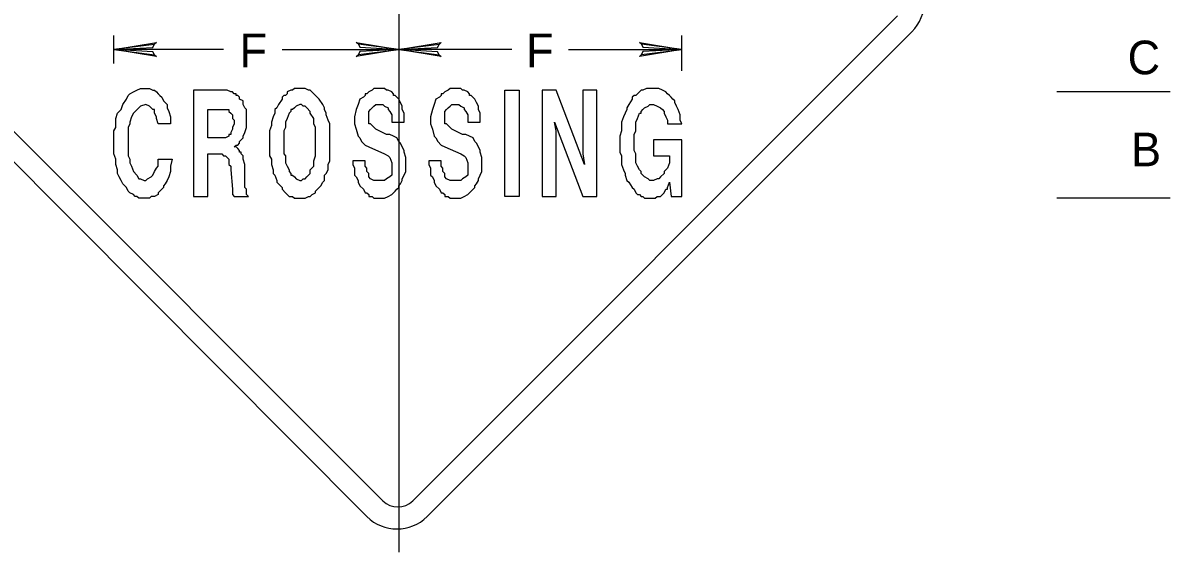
# Model space of a CAD drawing. Extents: x 0.013 to 0.191, y 0.004 to 0.259.
# Drawn here: x 0.0806 to 0.1616, y 0.1184 to 0.1557 of the extents above; entities that cross this region are included whole.
import ezdxf

# ---------------------------------------------------------------- set-up
doc = ezdxf.new("R2010")
doc.units = 0
doc.layers.add('1', color=7, linetype='Continuous')
doc.layers.add('3', color=7, linetype='Continuous')

# ---------------------------------------------------------------- blocks, each defined once
blk = doc.blocks.new('RARROW')
at = {"layer": '3'}
for p, q in [((-2.156, 0.28500000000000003), (-2.2665, 0.384625)), ((-2.2665, 0.384625), (0, 0)), ((0, 0), (-2.2665, -0.379125)), ((-2.156, 0.28500000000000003), (-2.075625, 0.12075)), ((0, 0), (-2.156, 0.28500000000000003)), ((-2.14975, -0.2705), (0, 0)), ((-2.075625, 0.12075), (0, 0)), ((0, 0), (-2.074, -0.108)), ((-2.2665, -0.379125), (-2.14975, -0.2705)), ((-2.074, -0.108), (-2.14975, -0.2705))]:
    blk.add_line(p, q, dxfattribs=at)

msp = doc.modelspace()

# ---------------------------------------------------------------- linework, layer by layer
at = {"layer": '1'}
for p, q in [((0.161625, 0.150875), (0.153625, 0.150875)), ((0.161625, 0.143375), (0.153625, 0.143375))]:
    msp.add_line(p, q, dxfattribs=at)
msp.add_lwpolyline([(0.125, 0.151125), (0.124875, 0.151125)], dxfattribs=at)
at = {"layer": '3'}
for p, q in [((0.107125, 0.1975), (0.107125, 0.11837500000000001)), ((0.107125, 0.15687500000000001), (0.107125, 0.154875)), ((0.106, 0.122), (0.07175000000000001, 0.15625)), ((0.142375, 0.15625), (0.108125, 0.122)), ((0.104875, 0.120875), (0.07062500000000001, 0.15525)), ((0.08700000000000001, 0.152875), (0.08700000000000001, 0.154875)), ((0.143375, 0.155125), (0.109125, 0.120875)), ((0.12712500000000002, 0.152375), (0.12712500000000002, 0.154875)), ((0.09475, 0.153875), (0.08700000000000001, 0.153875)), ((0.098875, 0.153875), (0.107125, 0.153875)), ((0.115125, 0.153875), (0.107125, 0.153875)), ((0.11912500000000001, 0.153875), (0.12712500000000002, 0.153875))]:
    msp.add_line(p, q, dxfattribs=at)
for points in [[(0.08700000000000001, 0.147375), (0.08700000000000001, 0.14775), (0.08700000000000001, 0.148125), (0.08712500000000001, 0.148375), (0.08712500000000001, 0.148625), (0.08712500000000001, 0.149), (0.08725000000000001, 0.149375), (0.08750000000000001, 0.149625), (0.08762500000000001, 0.15), (0.08787500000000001, 0.150375), (0.088, 0.150625), (0.088125, 0.15075), (0.088375, 0.150875), (0.088625, 0.151), (0.088875, 0.151125), (0.089125, 0.151125), (0.08925, 0.151125), (0.0895, 0.151125), (0.08975, 0.151), (0.089875, 0.151), (0.09, 0.150875), (0.090125, 0.15075), (0.09025, 0.150625), (0.090375, 0.1505), (0.0905, 0.15025), (0.09075, 0.15), (0.09075, 0.14975), (0.090875, 0.1495), (0.091, 0.149125), (0.091, 0.148625)], [(0.095, 0.151), (0.092625, 0.151), (0.092625, 0.14350000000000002), (0.093625, 0.14350000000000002), (0.093625, 0.1465), (0.0945, 0.1465)], [(0.0965, 0.14350000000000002), (0.096375, 0.143625), (0.096375, 0.14375000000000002), (0.096375, 0.14400000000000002), (0.09625, 0.144125), (0.09625, 0.14425), (0.09625, 0.145625), (0.09625, 0.14575), (0.096125, 0.146125), (0.096125, 0.14625), (0.096125, 0.146375), (0.096, 0.1465), (0.096, 0.146625), (0.095875, 0.146625), (0.095875, 0.14675), (0.09575, 0.146875), (0.09575, 0.146875), (0.095625, 0.147), (0.0955, 0.147), (0.095625, 0.147125), (0.09575, 0.147125), (0.095875, 0.14725), (0.095875, 0.147375), (0.096125, 0.147625), (0.096125, 0.14775), (0.09625, 0.148), (0.096375, 0.148375), (0.096375, 0.1485), (0.096375, 0.148625), (0.096375, 0.148875), (0.096375, 0.149125), (0.096375, 0.149375), (0.096375, 0.149625), (0.09625, 0.14975), (0.096125, 0.15), (0.096125, 0.15), (0.096125, 0.15025), (0.095875, 0.150375), (0.095875, 0.1505), (0.09575, 0.150625), (0.095625, 0.150625), (0.095625, 0.15075), (0.0955, 0.15075), (0.095375, 0.150875), (0.09525, 0.150875), (0.095, 0.151)], [(0.100125, 0.151125), (0.09975, 0.151125), (0.099625, 0.151), (0.0995, 0.151), (0.09925, 0.150875), (0.09925, 0.15075), (0.099125, 0.150625), (0.099, 0.150625), (0.098875, 0.1505), (0.098875, 0.150375), (0.098625, 0.15), (0.0985, 0.14975), (0.098375, 0.149625), (0.098375, 0.149375), (0.09825, 0.149125), (0.098125, 0.14875), (0.098125, 0.1485), (0.098, 0.148125), (0.098, 0.147625), (0.098, 0.147375), (0.098, 0.14725)], [(0.10225000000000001, 0.14725), (0.10225000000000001, 0.147625), (0.10225000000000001, 0.14775), (0.10225000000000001, 0.148125), (0.10225000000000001, 0.148375), (0.10225000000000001, 0.148625), (0.10212500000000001, 0.148875), (0.10200000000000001, 0.14925), (0.10200000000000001, 0.149375), (0.10187500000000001, 0.149625), (0.10187500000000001, 0.14975), (0.10175000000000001, 0.15), (0.1015, 0.150375), (0.10125, 0.150625), (0.101125, 0.15075), (0.100875, 0.151), (0.10075, 0.151), (0.1005, 0.151125), (0.10025, 0.151125), (0.100125, 0.151125)], [(0.106875, 0.150625), (0.10675, 0.150625), (0.10675, 0.15075), (0.106625, 0.150875), (0.106375, 0.151), (0.10625, 0.151), (0.106125, 0.151125), (0.105875, 0.151125), (0.10575, 0.151125), (0.105625, 0.151125), (0.105375, 0.151125), (0.10525, 0.151), (0.105, 0.150875), (0.104875, 0.15075), (0.10475, 0.15075), (0.10475, 0.150625), (0.104625, 0.1505)], [(0.11225, 0.150625), (0.112125, 0.150625), (0.112125, 0.15075), (0.112, 0.150875), (0.11175, 0.151), (0.111625, 0.151), (0.1115, 0.151125), (0.11125, 0.151125), (0.111125, 0.151125), (0.111, 0.151125), (0.11075, 0.151125), (0.110625, 0.151), (0.110375, 0.150875), (0.11025, 0.15075), (0.110125, 0.15075), (0.110125, 0.150625), (0.11, 0.1505)], [(0.114625, 0.14350000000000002), (0.114625, 0.151), (0.115625, 0.151), (0.115625, 0.14350000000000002), (0.114625, 0.14350000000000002)], [(0.11725000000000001, 0.151), (0.11725000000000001, 0.14350000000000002), (0.11825000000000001, 0.14350000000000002), (0.11825000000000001, 0.148125), (0.11812500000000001, 0.14875), (0.120125, 0.14350000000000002), (0.121125, 0.14350000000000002), (0.121125, 0.151), (0.120125, 0.151), (0.120125, 0.1465), (0.12025, 0.14575), (0.11825000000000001, 0.151), (0.11725000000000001, 0.151)], [(0.125, 0.151125), (0.124625, 0.151125), (0.124375, 0.151), (0.12425, 0.151), (0.124125, 0.150875), (0.124, 0.15075), (0.123875, 0.150625), (0.12375, 0.150625), (0.123625, 0.1505), (0.123625, 0.150375), (0.123375, 0.15), (0.12325, 0.14975), (0.12325, 0.149625), (0.123125, 0.149375), (0.123, 0.149125), (0.122875, 0.14875), (0.122875, 0.1485), (0.122875, 0.148125), (0.12275, 0.14775), (0.12275, 0.147375), (0.12275, 0.14725)], [(0.12712500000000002, 0.148625), (0.127, 0.148875), (0.127, 0.149125), (0.127, 0.14925), (0.12687500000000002, 0.149625), (0.12675, 0.149875), (0.12662500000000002, 0.150125), (0.12662500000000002, 0.15025), (0.1265, 0.150375), (0.12637500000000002, 0.1505), (0.12625, 0.150625), (0.12612500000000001, 0.15075), (0.126, 0.150875), (0.126, 0.150875), (0.12575, 0.151), (0.1255, 0.151125), (0.12525, 0.151125), (0.125, 0.151125)], [(0.090125, 0.148625), (0.09, 0.149), (0.09, 0.149125), (0.089875, 0.149375), (0.089875, 0.149625), (0.08975, 0.149625), (0.089625, 0.14975), (0.0895, 0.149875), (0.0895, 0.149875), (0.08925, 0.15), (0.08925, 0.15), (0.088875, 0.149875), (0.08875, 0.14975), (0.0885, 0.1495), (0.088375, 0.149375), (0.08825, 0.149125), (0.088125, 0.14875), (0.088125, 0.148625), (0.088, 0.148375), (0.088, 0.148125), (0.088, 0.14775), (0.088, 0.1475)], [(0.10025, 0.15), (0.100125, 0.15), (0.099875, 0.149875), (0.09975, 0.14975), (0.099625, 0.149625), (0.0995, 0.149625), (0.0995, 0.1495), (0.099375, 0.149375), (0.099375, 0.149375), (0.09925, 0.149), (0.099125, 0.14875), (0.099125, 0.1485), (0.099125, 0.148375), (0.099, 0.148125), (0.099, 0.147875), (0.099, 0.147625), (0.099, 0.1475), (0.099, 0.147375)], [(0.10125, 0.147375), (0.10125, 0.1475), (0.10125, 0.14775), (0.10125, 0.148), (0.10125, 0.148375), (0.101125, 0.148625), (0.101125, 0.149), (0.100875, 0.149375), (0.100875, 0.1495), (0.100625, 0.14975), (0.1005, 0.149875), (0.100375, 0.149875), (0.10025, 0.15), (0.10025, 0.15)], [(0.104625, 0.1505), (0.104375, 0.150375), (0.10425, 0.15), (0.104125, 0.149625), (0.10400000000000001, 0.149125), (0.10400000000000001, 0.148625), (0.104125, 0.14825), (0.10425, 0.14775), (0.104375, 0.147625), (0.1045, 0.147375), (0.10475, 0.147125), (0.105, 0.147), (0.106125, 0.1465), (0.106375, 0.146375), (0.1065, 0.14625), (0.106625, 0.145875), (0.106625, 0.145625), (0.106625, 0.1455)], [(0.105, 0.149), (0.105, 0.14925), (0.105, 0.1495), (0.105125, 0.149625), (0.10525, 0.14975), (0.105375, 0.149875), (0.1055, 0.15), (0.10575, 0.15), (0.106, 0.15), (0.106125, 0.149875), (0.106375, 0.14975), (0.106375, 0.149625), (0.1065, 0.1495), (0.106625, 0.14925), (0.106625, 0.14875)], [(0.106625, 0.14875), (0.1075, 0.14875), (0.1075, 0.149125), (0.1075, 0.149375), (0.107375, 0.149625), (0.107375, 0.149875), (0.10725, 0.150125), (0.107125, 0.150375), (0.106875, 0.150625)], [(0.11, 0.1505), (0.10975, 0.150375), (0.109625, 0.15), (0.1095, 0.149625), (0.109375, 0.149125), (0.109375, 0.148625), (0.1095, 0.14825), (0.109625, 0.14775), (0.10975, 0.147625), (0.109875, 0.147375), (0.110125, 0.147125), (0.110375, 0.147), (0.1115, 0.1465), (0.11175, 0.146375), (0.111875, 0.14625), (0.112, 0.145875), (0.112, 0.145625), (0.112, 0.1455)], [(0.110375, 0.149), (0.110375, 0.14925), (0.110375, 0.1495), (0.1105, 0.149625), (0.110625, 0.14975), (0.11075, 0.149875), (0.110875, 0.15), (0.111125, 0.15), (0.111375, 0.15), (0.1115, 0.149875), (0.11175, 0.14975), (0.11175, 0.149625), (0.111875, 0.1495), (0.112, 0.14925), (0.112, 0.14875)], [(0.112, 0.14875), (0.112875, 0.14875), (0.112875, 0.149125), (0.112875, 0.149375), (0.11275, 0.149625), (0.11275, 0.149875), (0.112625, 0.150125), (0.1125, 0.150375), (0.11225, 0.150625)], [(0.12375, 0.147375), (0.12375, 0.1475), (0.12375, 0.147625), (0.12375, 0.147875), (0.123875, 0.148125), (0.123875, 0.148375), (0.123875, 0.1485), (0.123875, 0.14875), (0.124, 0.149), (0.124125, 0.149375), (0.12425, 0.149375), (0.12425, 0.1495), (0.124375, 0.149625), (0.124375, 0.149625), (0.1245, 0.14975), (0.12475, 0.149875), (0.124875, 0.15), (0.125, 0.15)], [(0.125, 0.15), (0.12512500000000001, 0.15), (0.12537500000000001, 0.149875), (0.12562500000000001, 0.14975), (0.12575, 0.149625), (0.12587500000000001, 0.1495), (0.12587500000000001, 0.149375), (0.126, 0.149125), (0.12612500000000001, 0.148875), (0.12612500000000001, 0.148625)], [(0.094875, 0.147625), (0.093625, 0.147625), (0.093625, 0.149625), (0.094875, 0.149625)], [(0.094875, 0.149625), (0.095, 0.149625), (0.095125, 0.149625), (0.095125, 0.1495), (0.09525, 0.149375), (0.095375, 0.14925), (0.095375, 0.149125), (0.095375, 0.149), (0.0955, 0.148875), (0.0955, 0.148625), (0.0955, 0.148625), (0.095375, 0.148375), (0.095375, 0.14825), (0.09525, 0.148), (0.09525, 0.147875), (0.095125, 0.147875), (0.095125, 0.14775), (0.094875, 0.147625), (0.094875, 0.147625)], [(0.091, 0.148625), (0.090125, 0.148625)], [(0.1075, 0.145), (0.1075, 0.145), (0.107625, 0.14525), (0.107625, 0.1455), (0.107625, 0.145875), (0.107625, 0.146), (0.107625, 0.14625), (0.1075, 0.146625), (0.1075, 0.14675), (0.107375, 0.147), (0.10725, 0.14725), (0.107125, 0.147375), (0.107, 0.147625), (0.10675, 0.14775), (0.1065, 0.147875), (0.10625, 0.147875), (0.1055, 0.14825), (0.10525, 0.1485), (0.105125, 0.148625), (0.105, 0.148625), (0.105, 0.148875), (0.105, 0.149)], [(0.112875, 0.145), (0.112875, 0.145), (0.113, 0.14525), (0.113, 0.1455), (0.113, 0.145875), (0.113, 0.146), (0.113, 0.14625), (0.112875, 0.146625), (0.112875, 0.14675), (0.11275, 0.147), (0.112625, 0.14725), (0.1125, 0.147375), (0.112375, 0.147625), (0.112125, 0.14775), (0.111875, 0.147875), (0.111625, 0.147875), (0.110875, 0.14825), (0.110625, 0.1485), (0.1105, 0.148625), (0.110375, 0.148625), (0.110375, 0.148875), (0.110375, 0.149)], [(0.12612500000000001, 0.148625), (0.12712500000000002, 0.148625)], [(0.091125, 0.146125), (0.091, 0.145625), (0.091, 0.14525), (0.090875, 0.144875), (0.09075, 0.144625), (0.090625, 0.144375), (0.0905, 0.14425), (0.0905, 0.144125), (0.090375, 0.14400000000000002), (0.09025, 0.143875), (0.090125, 0.14375000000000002), (0.090125, 0.143625), (0.089875, 0.14350000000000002), (0.089875, 0.14350000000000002), (0.089625, 0.14350000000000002), (0.0895, 0.143375), (0.08925, 0.143375), (0.089, 0.143375), (0.08875, 0.143375), (0.088625, 0.14350000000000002), (0.0885, 0.14350000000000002), (0.088375, 0.143625), (0.088125, 0.14375000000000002), (0.088125, 0.14375000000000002), (0.088, 0.143875), (0.08787500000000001, 0.144125), (0.08762500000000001, 0.144375), (0.08750000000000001, 0.144625), (0.08737500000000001, 0.144875), (0.08725000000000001, 0.145125), (0.08725000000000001, 0.145375), (0.08712500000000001, 0.14575), (0.08712500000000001, 0.146125), (0.08700000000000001, 0.1465), (0.08700000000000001, 0.146875), (0.08700000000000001, 0.147375)], [(0.088, 0.1475), (0.088, 0.1475), (0.088, 0.147125), (0.088, 0.147), (0.088, 0.146625), (0.088, 0.146375), (0.088125, 0.146125), (0.088125, 0.145875), (0.08825, 0.145625), (0.088375, 0.14525), (0.088625, 0.145), (0.08875, 0.14475), (0.088875, 0.14475), (0.089125, 0.144625), (0.08925, 0.144625), (0.089375, 0.14475), (0.089625, 0.144875), (0.08975, 0.145), (0.089875, 0.14525), (0.09, 0.1455), (0.090125, 0.145625), (0.090125, 0.146125)], [(0.098, 0.14725), (0.098, 0.147), (0.098, 0.14675), (0.098, 0.146375), (0.098125, 0.146125), (0.098125, 0.145875), (0.098125, 0.14575), (0.09825, 0.145375), (0.09825, 0.145125), (0.098375, 0.145), (0.0985, 0.144625), (0.0985, 0.1445), (0.098875, 0.144125), (0.098875, 0.14400000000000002), (0.099125, 0.14375000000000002), (0.09925, 0.143625), (0.09925, 0.143625), (0.099375, 0.14350000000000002), (0.0995, 0.14350000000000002), (0.099625, 0.14350000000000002), (0.09975, 0.143375), (0.1, 0.143375), (0.10025, 0.143375), (0.10025, 0.143375), (0.1005, 0.143375), (0.10075, 0.14350000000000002), (0.100875, 0.14350000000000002), (0.101, 0.143625), (0.10125, 0.14375000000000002), (0.10125, 0.143875), (0.101375, 0.14400000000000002), (0.10162500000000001, 0.14425), (0.10175000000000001, 0.1445), (0.10187500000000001, 0.144625), (0.10187500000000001, 0.145), (0.10200000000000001, 0.145125), (0.10212500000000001, 0.145375), (0.10212500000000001, 0.14575), (0.10225000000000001, 0.146), (0.10225000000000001, 0.14625), (0.10225000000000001, 0.14675), (0.10225000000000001, 0.14725)], [(0.099, 0.147375), (0.099, 0.14725), (0.099, 0.147), (0.099, 0.14675), (0.099, 0.1465), (0.099125, 0.146375), (0.099125, 0.146125), (0.099125, 0.145875), (0.09925, 0.145625), (0.099375, 0.145375), (0.099375, 0.14525), (0.0995, 0.145125), (0.0995, 0.145), (0.099625, 0.145), (0.09975, 0.144875), (0.099875, 0.14475), (0.100125, 0.144625), (0.10025, 0.144625)], [(0.10025, 0.144625), (0.10025, 0.144625), (0.100375, 0.14475), (0.1005, 0.14475), (0.100625, 0.144875), (0.100875, 0.145125), (0.100875, 0.145375), (0.101125, 0.145625), (0.101125, 0.146), (0.10125, 0.146375), (0.10125, 0.146625), (0.10125, 0.146875), (0.10125, 0.14725), (0.10125, 0.147375)], [(0.12275, 0.14725), (0.12275, 0.147), (0.12275, 0.146625), (0.122875, 0.146375), (0.122875, 0.146125), (0.122875, 0.145875), (0.122875, 0.14575), (0.123, 0.145375), (0.123125, 0.145125), (0.123125, 0.145), (0.12325, 0.144625), (0.123375, 0.1445), (0.123625, 0.144125), (0.12375, 0.14400000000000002), (0.123875, 0.14375000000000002), (0.124, 0.143625), (0.124125, 0.143625), (0.12425, 0.14350000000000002), (0.12425, 0.14350000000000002), (0.124375, 0.14350000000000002), (0.1245, 0.143375), (0.12475, 0.143375), (0.125, 0.143375)], [(0.125, 0.144625), (0.124875, 0.144625), (0.12475, 0.14475), (0.1245, 0.144875), (0.124375, 0.145), (0.124375, 0.145), (0.12425, 0.145125), (0.12425, 0.14525), (0.124125, 0.145375), (0.124, 0.145625), (0.123875, 0.145875), (0.123875, 0.146125), (0.123875, 0.146375), (0.123875, 0.1465), (0.12375, 0.14675), (0.12375, 0.147), (0.12375, 0.14725), (0.12375, 0.147375)], [(0.12625, 0.1445), (0.12637500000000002, 0.14350000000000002), (0.12712500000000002, 0.14350000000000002), (0.12712500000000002, 0.1475), (0.12512500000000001, 0.1475), (0.12512500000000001, 0.146375), (0.12625, 0.146375)], [(0.090125, 0.146125), (0.091125, 0.146125)], [(0.0945, 0.1465), (0.094625, 0.1465), (0.09475, 0.146375), (0.094875, 0.146375), (0.095, 0.14625), (0.095125, 0.146125), (0.095125, 0.145875), (0.095125, 0.14575), (0.09525, 0.145625), (0.09525, 0.145375), (0.095375, 0.14400000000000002), (0.095375, 0.14400000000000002), (0.095375, 0.14375000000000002), (0.095375, 0.143625), (0.0955, 0.14350000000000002), (0.0955, 0.14350000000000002)], [(0.10475, 0.145875), (0.10475, 0.146), (0.10387500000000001, 0.146)], [(0.10387500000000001, 0.146), (0.10387500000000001, 0.14575), (0.10400000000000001, 0.1455), (0.10400000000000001, 0.14525), (0.10400000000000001, 0.145125), (0.10400000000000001, 0.145), (0.104125, 0.144875), (0.10425, 0.144625), (0.10425, 0.1445)], [(0.110125, 0.145875), (0.110125, 0.146), (0.10925, 0.146)], [(0.10925, 0.146), (0.10925, 0.14575), (0.109375, 0.1455), (0.109375, 0.14525), (0.109375, 0.145125), (0.109375, 0.145), (0.1095, 0.144875), (0.109625, 0.144625), (0.109625, 0.1445)], [(0.12625, 0.146375), (0.12625, 0.146125), (0.12625, 0.145875), (0.12612500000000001, 0.1455), (0.126, 0.145375), (0.12587500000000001, 0.14525), (0.12587500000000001, 0.145125), (0.12562500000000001, 0.144875), (0.1255, 0.14475), (0.12537500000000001, 0.14475), (0.12512500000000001, 0.144625), (0.125, 0.144625)], [(0.10625, 0.14475), (0.106125, 0.144625), (0.105875, 0.144625), (0.10575, 0.144625), (0.105625, 0.144625), (0.105375, 0.144625), (0.105125, 0.14475), (0.105, 0.144875), (0.105, 0.145125), (0.104875, 0.14525), (0.104875, 0.1455), (0.10475, 0.145625), (0.10475, 0.145875)], [(0.106625, 0.1455), (0.106625, 0.14525), (0.106625, 0.145), (0.1065, 0.144875), (0.10625, 0.14475)], [(0.111625, 0.14475), (0.1115, 0.144625), (0.11125, 0.144625), (0.111125, 0.144625), (0.111, 0.144625), (0.11075, 0.144625), (0.1105, 0.14475), (0.110375, 0.144875), (0.110375, 0.145125), (0.11025, 0.14525), (0.11025, 0.1455), (0.110125, 0.145625), (0.110125, 0.145875)], [(0.112, 0.1455), (0.112, 0.14525), (0.112, 0.145), (0.111875, 0.144875), (0.111625, 0.14475)], [(0.10425, 0.1445), (0.104375, 0.14425), (0.104625, 0.14400000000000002), (0.10475, 0.14375000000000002), (0.104875, 0.14375000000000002), (0.105, 0.143625), (0.105, 0.14350000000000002), (0.105125, 0.14350000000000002), (0.10525, 0.14350000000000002), (0.105375, 0.143375), (0.105625, 0.143375), (0.10575, 0.143375), (0.105875, 0.143375), (0.106125, 0.143375), (0.106375, 0.14350000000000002), (0.106375, 0.14350000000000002), (0.106625, 0.143625), (0.10675, 0.14375000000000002), (0.106875, 0.143875), (0.107, 0.14400000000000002), (0.107125, 0.144125), (0.107125, 0.14425), (0.10725, 0.144375), (0.107375, 0.144625), (0.107375, 0.14475), (0.1075, 0.145)], [(0.109625, 0.1445), (0.10975, 0.14425), (0.11, 0.14400000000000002), (0.110125, 0.14375000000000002), (0.11025, 0.14375000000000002), (0.110375, 0.143625), (0.110375, 0.14350000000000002), (0.1105, 0.14350000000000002), (0.110625, 0.14350000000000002), (0.11075, 0.143375), (0.111, 0.143375), (0.111125, 0.143375), (0.11125, 0.143375), (0.1115, 0.143375), (0.11175, 0.14350000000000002), (0.11175, 0.14350000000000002), (0.112, 0.143625), (0.112125, 0.14375000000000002), (0.11225, 0.143875), (0.112375, 0.14400000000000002), (0.1125, 0.144125), (0.1125, 0.14425), (0.112625, 0.144375), (0.11275, 0.144625), (0.11275, 0.14475), (0.112875, 0.145)], [(0.125, 0.143375), (0.125, 0.143375), (0.12525, 0.143375), (0.12537500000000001, 0.14350000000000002), (0.12562500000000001, 0.14350000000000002), (0.12562500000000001, 0.14350000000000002), (0.12575, 0.143625), (0.12575, 0.143625), (0.12587500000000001, 0.14375000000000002), (0.126, 0.14400000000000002), (0.12612500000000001, 0.14400000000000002), (0.12612500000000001, 0.144125), (0.12625, 0.1445)], [(0.0955, 0.14350000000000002), (0.0965, 0.14350000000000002)]]:
    msp.add_lwpolyline(points, dxfattribs=at)
for centre, radius, start, end in [((0.14120663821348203, 0.15731249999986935), 0.0030800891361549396, 314.74826388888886, 45.25173888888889), ((0.10706250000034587, 0.12308097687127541), 0.001515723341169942, 225.4938805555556, 314.5061194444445), ((0.10700000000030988, 0.12303695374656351), 0.0030314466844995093, 225.4938805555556, 314.5061194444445)]:
    msp.add_arc(centre, radius, start, end, dxfattribs=at)

# ---------------------------------------------------------------- block references
at = {"layer": '3', "xscale": 0.0013236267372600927, "yscale": 0.001309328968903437, "rotation": 180}
for p in [(0.08700000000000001, 0.153875), (0.107125, 0.153875)]:
    msp.add_blockref('RARROW', p, dxfattribs=at)
at = {"layer": '3', "xscale": 0.0013236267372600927, "yscale": 0.001309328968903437}
for p in [(0.107125, 0.153875), (0.12712500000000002, 0.153875)]:
    msp.add_blockref('RARROW', p, dxfattribs=at)

# ---------------------------------------------------------------- texts
at = {"layer": '1'}
for s, p in [('C', (0.15862500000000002, 0.152125)), ('B', (0.15887500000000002, 0.145625))]:
    msp.add_text(s, height=0.0023752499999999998, dxfattribs=at).set_placement(p)
at = {"layer": '3'}
for p in [(0.095875, 0.152625), (0.116125, 0.152625)]:
    msp.add_text('F ', height=0.0023752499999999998, dxfattribs=at).set_placement(p)

doc.saveas('drawing.dxf')
